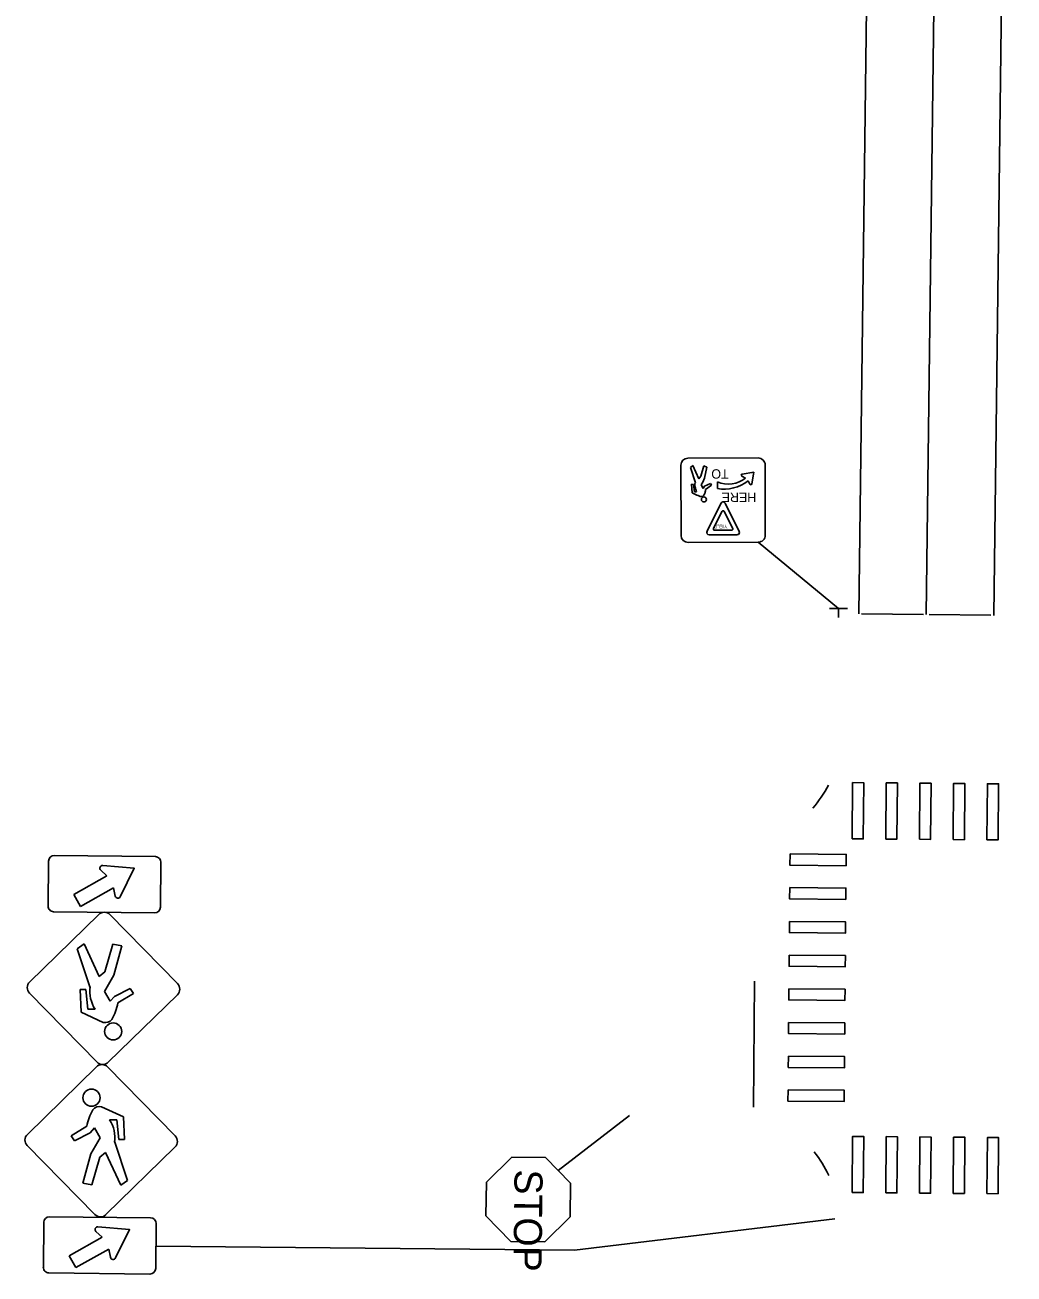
# Model space of a CAD drawing. Extents: x 1652376 to 1652707, y 605933 to 608571.
# Drawn here: x 1652376 to 1652552.1, y 606819.4 to 607041.8 of the extents above; entities that cross this region are included whole.
import ezdxf

# ---------------------------------------------------------------- set-up
doc = ezdxf.new("R2010")
doc.units = 0
for name, color, linetype in [('_CIVIL_CONSTRUCTION', 7, 'Continuous'), ('GE_P_Alignment', 7, 'Continuous'), ('PM_P_CL_Double_Solid', 7, 'Continuous'), ('PV_P_EOP', 7, 'Continuous'), ('SH_Border', 7, 'Continuous'), ('SH_Cut_Line', 7, 'Continuous'), ('SN_P_Signs', 7, 'Continuous'), ('SN_P_Text', 7, 'Continuous'), ('SN_X_Public', 7, 'Continuous'), ('UT_X_Misc_Cells', 7, 'Continuous')]:
    doc.layers.add(name, color=color, linetype=linetype)

msp = doc.modelspace()

# ---------------------------------------------------------------- linework, layer by layer
at = {"layer": '_CIVIL_CONSTRUCTION'}
for points in [[(1652523.24, 606896.95), (1652525.24, 606896.93), (1652525.33, 606906.93), (1652523.33, 606906.95)], [(1652529.24, 606896.9), (1652531.24, 606896.88), (1652531.33, 606906.88), (1652529.33, 606906.9)], [(1652535.24, 606896.85), (1652537.24, 606896.83), (1652537.33, 606906.83), (1652535.33, 606906.85)], [(1652541.24, 606896.8), (1652543.24, 606896.78), (1652543.33, 606906.78), (1652541.33, 606906.8)], [(1652547.24, 606896.75), (1652549.24, 606896.73), (1652549.33, 606906.73), (1652547.33, 606906.75)], [(1652512.21, 606894.24), (1652512.19, 606892.24), (1652522.19, 606892.15), (1652522.21, 606894.15)], [(1652512.16, 606888.24), (1652512.14, 606886.24), (1652522.14, 606886.15), (1652522.16, 606888.15)], [(1652512.11, 606882.24), (1652512.09, 606880.24), (1652522.09, 606880.15), (1652522.11, 606882.15)], [(1652512.06, 606876.24), (1652512.04, 606874.24), (1652522.04, 606874.15), (1652522.06, 606876.15)], [(1652512.01, 606870.24), (1652511.99, 606868.24), (1652521.99, 606868.15), (1652522.01, 606870.15)], [(1652511.96, 606864.24), (1652511.94, 606862.24), (1652521.94, 606862.15), (1652521.96, 606864.15)], [(1652511.91, 606858.24), (1652511.89, 606856.24), (1652521.89, 606856.15), (1652521.91, 606858.15)], [(1652511.85, 606852.24), (1652511.84, 606850.24), (1652521.84, 606850.15), (1652521.85, 606852.15)], [(1652523.24, 606833.95), (1652525.24, 606833.93), (1652525.33, 606843.93), (1652523.33, 606843.95)], [(1652529.24, 606833.9), (1652531.24, 606833.88), (1652531.33, 606843.88), (1652529.33, 606843.9)], [(1652535.24, 606833.85), (1652537.24, 606833.83), (1652537.33, 606843.83), (1652535.33, 606843.85)], [(1652541.24, 606833.8), (1652543.24, 606833.78), (1652543.33, 606843.78), (1652541.33, 606843.8)], [(1652547.24, 606833.75), (1652549.24, 606833.73), (1652549.33, 606843.73), (1652547.33, 606843.75)]]:
    msp.add_lwpolyline(points, close=True, dxfattribs=at)
at = {"layer": 'GE_P_Alignment'}
msp.add_lwpolyline([(1652536.46, 606936.85), (1652539.76, 607199.49), (1652540.08, 607225.63)], dxfattribs=at)
at = {"layer": 'PM_P_CL_Double_Solid'}
msp.add_lwpolyline([(1652524.46, 606937), (1652527.76, 607199.63), (1652528.08, 607225.77)], dxfattribs=at)
for centre, radius, start, end in [((1652492.93, 606921.21), 30, 321.1144, 330.6067), ((1652496.66, 606826.03), 25, 26.0343, 37.3992)]:
    msp.add_arc(centre, radius, start, end, dxfattribs=at)
at = {"layer": 'PV_P_EOP'}
msp.add_lwpolyline([(1652548.46, 606936.71), (1652551.76, 607199.34), (1652552.08, 607225.48)], dxfattribs=at)
at = {"layer": 'SH_Border'}
for p, q in [((1652389.88, 606892.17), (1652389.88, 606892.17)), ((1652384.74, 606887.02), (1652390.6, 606890.32)), ((1652390.6, 606890.32), (1652389.51, 606891.33)), ((1652391.79, 606888.2), (1652385.93, 606884.9)), ((1652392.09, 606886.75), (1652391.79, 606888.2)), ((1652385.93, 606884.9), (1652384.74, 606887.02)), ((1652385.35, 606877.37), (1652386.55, 606878.23)), ((1652386.55, 606878.23), (1652389.25, 606872.39)), ((1652390.25, 606873.25), (1652391.69, 606878.17)), ((1652391.69, 606878.17), (1652393.28, 606877.86)), ((1652387.65, 606870.38), (1652385.35, 606877.37)), ((1652393.28, 606877.86), (1652391.83, 606872.66)), ((1652389.25, 606872.39), (1652390.25, 606873.25)), ((1652391.83, 606872.66), (1652390.22, 606869.77)), ((1652386.02, 606866.04), (1652385.86, 606870.11)), ((1652385.86, 606870.11), (1652386.85, 606870.09)), ((1652386.85, 606870.09), (1652387.21, 606866.6)), ((1652390.22, 606869.77), (1652391.19, 606868.01)), ((1652391.99, 606868.88), (1652394.78, 606870.3)), ((1652395.36, 606869.42), (1652392.57, 606867.71)), ((1652394.78, 606870.3), (1652395.36, 606869.42)), ((1652391.19, 606868.01), (1652391.99, 606868.88)), ((1652389.96, 606864.25), (1652386.02, 606866.04)), ((1652387.21, 606866.6), (1652388.52, 606866.59)), ((1652389.66, 606849.22), (1652393.6, 606847.44)), ((1652393.6, 606847.44), (1652393.75, 606843.37)), ((1652384.26, 606844.06), (1652387.05, 606845.77)), ((1652388.43, 606845.46), (1652387.63, 606844.6)), ((1652389.4, 606843.71), (1652388.43, 606845.46)), ((1652392.41, 606846.87), (1652391.1, 606846.89)), ((1652392.76, 606843.38), (1652392.41, 606846.87)), ((1652384.84, 606843.18), (1652384.26, 606844.06)), ((1652387.63, 606844.6), (1652384.84, 606843.18)), ((1652387.78, 606840.82), (1652389.4, 606843.71)), ((1652391.97, 606843.1), (1652394.27, 606836.1)), ((1652393.75, 606843.37), (1652392.76, 606843.38)), ((1652386.34, 606835.61), (1652387.78, 606840.82)), ((1652390.36, 606841.09), (1652389.36, 606840.22)), ((1652393.07, 606835.25), (1652390.36, 606841.09)), ((1652389.36, 606840.22), (1652387.92, 606835.31)), ((1652462.71, 606840.23), (1652458.16, 606835.78)), ((1652468.71, 606840.16), (1652462.71, 606840.23)), ((1652473.16, 606835.61), (1652468.71, 606840.16)), ((1652394.27, 606836.1), (1652393.07, 606835.25)), ((1652387.92, 606835.31), (1652386.34, 606835.61)), ((1652458.16, 606835.78), (1652458.09, 606829.78)), ((1652473.09, 606829.61), (1652473.16, 606835.61)), ((1652458.09, 606829.78), (1652462.54, 606825.23)), ((1652468.54, 606825.16), (1652473.09, 606829.61)), ((1652389.75, 606826), (1652388.66, 606827.01)), ((1652389.03, 606827.85), (1652389.03, 606827.85)), ((1652383.89, 606822.7), (1652389.75, 606826)), ((1652462.54, 606825.23), (1652468.54, 606825.16)), ((1652385.08, 606820.58), (1652383.89, 606822.7)), ((1652390.94, 606823.88), (1652385.08, 606820.58)), ((1652391.24, 606822.43), (1652390.94, 606823.88))]:
    msp.add_line(p, q, dxfattribs=at)
for points in [[(1652399.25, 606893.76), (1652381.25, 606893.96)], [(1652380.24, 606892.97), (1652380.15, 606884.97)], [(1652389.88, 606892.17), (1652395.5, 606891.69), (1652393, 606886.63)], [(1652400.15, 606884.75), (1652400.24, 606892.75)], [(1652376.87, 606871.43), (1652389.17, 606883.46)], [(1652381.14, 606883.96), (1652399.14, 606883.76)], [(1652391.15, 606883.44), (1652403.18, 606871.15)], [(1652388.88, 606857.16), (1652376.85, 606869.45)], [(1652403.16, 606869.17), (1652390.86, 606857.14)], [(1652376.46, 606844.31), (1652388.76, 606856.34)], [(1652390.74, 606856.32), (1652402.76, 606844.02)], [(1652388.47, 606830.04), (1652376.44, 606842.33)], [(1652402.74, 606842.04), (1652390.45, 606830.01)], [(1652398.4, 606829.44), (1652380.4, 606829.64)], [(1652379.39, 606828.65), (1652379.31, 606820.65)], [(1652389.03, 606827.85), (1652394.65, 606827.36), (1652392.15, 606822.31)], [(1652399.3, 606820.43), (1652399.39, 606828.43)], [(1652380.29, 606819.64), (1652398.29, 606819.44)]]:
    msp.add_lwpolyline(points, dxfattribs=at)
for centre in [(1652391.74, 606862.64), (1652387.88, 606850.84)]:
    msp.add_circle(centre, 1.52, dxfattribs=at)
for centre, radius, start, end in [((1652381.24, 606892.96), 1, 89.3709, 179.3709), ((1652399.24, 606892.76), 1, 359.3709, 89.3709), ((1652389.84, 606891.69), 0.486, 85.0472, 227.1837), ((1652381.15, 606884.96), 1, 179.3709, 269.3709), ((1652392.57, 606886.84), 0.486, 191.5581, 333.6946), ((1652390.15, 606882.46), 1.4, 44.3709, 134.3709), ((1652399.15, 606884.76), 1, 269.3709, 359.3709), ((1652377.85, 606870.43), 1.4, 134.3709, 224.3709), ((1652393.23, 606869.7), 5.64, 171.2211, 213.4318), ((1652402.18, 606870.17), 1.4, 314.3709, 44.3709), ((1652383.04, 606869.49), 9.69, 330.912, 349.4026), ((1652390.33, 606865.71), 1.5, 255.615, 321.8659), ((1652389.73, 606855.34), 1.4, 44.3709, 134.3709), ((1652389.88, 606858.14), 1.4, 224.3709, 314.3709), ((1652389.29, 606847.77), 1.5, 75.615, 141.8659), ((1652396.57, 606843.98), 9.69, 150.912, 169.4026), ((1652386.39, 606843.77), 5.64, 351.2211, 33.4318), ((1652377.44, 606843.31), 1.4, 134.3709, 224.3709), ((1652401.76, 606843.04), 1.4, 314.3709, 44.3709), ((1652380.39, 606828.64), 1, 89.3709, 179.3709), ((1652389.47, 606831.01), 1.4, 224.3709, 314.3709), ((1652398.39, 606828.44), 1, 359.3709, 89.3709), ((1652388.99, 606827.36), 0.486, 85.0472, 227.1837), ((1652380.3, 606820.64), 1, 179.3709, 269.3709), ((1652391.72, 606822.52), 0.486, 191.5581, 333.6946), ((1652398.3, 606820.44), 1, 269.3709, 359.3709)]:
    msp.add_arc(centre, radius, start, end, dxfattribs=at)
at = {"layer": 'SH_Cut_Line'}
for p, q in [((1652535.95, 606936.86), (1652524.96, 606936.99)), ((1652547.95, 606936.76), (1652536.96, 606936.89))]:
    msp.add_line(p, q, dxfattribs=at)
at = {"layer": 'SN_P_Signs'}
msp.add_line((1652506.56, 606949.75), (1652520.83, 606937.92), dxfattribs=at)
at = {"layer": 'SN_P_Text'}
for p, q in [((1652494.93, 606963.41), (1652494.47, 606963.06)), ((1652494.47, 606963.06), (1652495.39, 606960.35)), ((1652495.96, 606961.06), (1652494.93, 606963.41)), ((1652496.87, 606963.37), (1652496.33, 606961.53)), ((1652497.4, 606963.11), (1652496.87, 606963.37)), ((1652496.98, 606961.14), (1652497.4, 606963.11)), ((1652496.33, 606961.53), (1652495.96, 606961.06)), ((1652496.42, 606959.99), (1652496.67, 606960.47)), ((1652496.67, 606960.47), (1652496.98, 606961.14)), ((1652499.28, 606959.29), (1652499.28, 606960.52)), ((1652504.3, 606961.18), (1652503.62, 606961.53)), ((1652503.67, 606961.87), (1652505.79, 606962.25)), ((1652505.08, 606960.08), (1652504.76, 606960.69)), ((1652505.79, 606962.25), (1652505.42, 606960.13)), ((1652495, 606960.05), (1652494.66, 606960.08)), ((1652494.66, 606960.08), (1652494.79, 606958.52)), ((1652494.79, 606958.52), (1652494.8, 606958.52)), ((1652495.19, 606958.73), (1652495, 606960.05)), ((1652495.57, 606958.72), (1652495.19, 606958.73)), ((1652495.39, 606960.35), (1652495.34, 606960.29)), ((1652496.77, 606959.29), (1652496.42, 606959.99)), ((1652497, 606959.72), (1652496.77, 606959.29)), ((1652498.03, 606960.21), (1652497, 606959.72)), ((1652497.19, 606959.12), (1652498.24, 606959.9)), ((1652498.24, 606959.9), (1652498.03, 606960.21)), ((1652500.65, 606956.7), (1652503.18, 606951.66)), ((1652500.51, 606955.23), (1652502.02, 606952.21)), ((1652498.8, 606951.87), (1652501.82, 606951.88)), ((1652502.83, 606951.09), (1652497.79, 606951.08)), ((1652499.8, 606951.08), (1652499.81, 606951.09)), ((1652502.77, 606951.09), (1652502.77, 606951.09)), ((1652519.23, 606937.92), (1652522.43, 606937.92)), ((1652520.83, 606937.92), (1652520.83, 606936.32))]:
    msp.add_line(p, q, dxfattribs=at)
for points in [[(1652492.78, 606963.46), (1652492.81, 606950.96)], [(1652506.52, 606964.75), (1652494.02, 606964.71)], [(1652507.81, 606951), (1652507.78, 606963.5)], [(1652497.43, 606951.65), (1652499.94, 606956.7)], [(1652498.59, 606952.21), (1652500.09, 606955.22)], [(1652494.06, 606949.71), (1652506.56, 606949.75)]]:
    msp.add_lwpolyline(points, dxfattribs=at)
msp.add_circle((1652496.89, 606957.36), 0.45, dxfattribs=at)
for centre, radius, start, end in [((1652494.03, 606963.46), 1.25, 90.1516, 180.1516), ((1652506.53, 606963.5), 1.25, 0.1516, 90.1516), ((1652501.26, 606964.94), 4.84, 245.8938, 309.0288), ((1652500.46, 606966.1), 6.91, 260.1665, 308.517), ((1652503.71, 606961.69), 0.181, 100.0723, 242.7894), ((1652505.24, 606960.16), 0.181, 207.5138, 350.2308), ((1652500.3, 606956.52), 0.395, 26.7166, 153.5865), ((1652500.3, 606955.12), 0.232, 26.7166, 153.5865), ((1652497.79, 606951.47), 0.395, 153.5865, 270.1516), ((1652498.8, 606952.1), 0.232, 153.5865, 270.1516), ((1652501.82, 606952.11), 0.232, 270.1516, 26.7166), ((1652502.83, 606951.49), 0.395, 270.1516, 26.7166), ((1652494.06, 606950.96), 1.25, 180.1516, 270.1516), ((1652506.56, 606951), 1.25, 270.1516, 0.1516)]:
    msp.add_arc(centre, radius, start, end, dxfattribs=at)
for points in [[(1652494.8, 606958.52), (1652495.26, 606958.32), (1652495.98, 606957.99), (1652496.24, 606957.87), (1652496.33, 606957.86), (1652496.42, 606957.86), (1652496.63, 606957.86), (1652496.89, 606958.11), (1652497.03, 606958.5), (1652497.16, 606958.79), (1652497.19, 606959.12)], [(1652495.34, 606960.29), (1652495.29, 606960.21), (1652495.24, 606960.08), (1652495.26, 606959.82), (1652495.31, 606959.6), (1652495.41, 606959.23), (1652495.49, 606958.96), (1652495.57, 606958.72)]]:
    msp.add_open_spline(points, degree=3, dxfattribs=at)
at = {"layer": 'SN_X_Public'}
msp.add_line((1652505.72, 606849.16), (1652505.91, 606871.6), dxfattribs=at)
at = {"layer": 'UT_X_Misc_Cells'}
msp.add_line((1652470.92, 606837.9), (1652483.66, 606847.67), dxfattribs=at)
msp.add_lwpolyline([(1652399.35, 606824.43), (1652473.87, 606823.7), (1652520.18, 606829.25)], dxfattribs=at)

# ---------------------------------------------------------------- texts
at = {"layer": 'SH_Border'}
msp.add_text('STOP', height=5, rotation=269.3709, dxfattribs=at).set_placement((1652463.18, 606838.09))
at = {"layer": 'SN_P_Text'}
for s, height, p in [('TO', 1.667, (1652501.29, 606962.75)), ('HERE', 1.667, (1652506.21, 606958.6)), ('YIELD', 0.608, (1652501.05, 606952.85))]:
    msp.add_text(s, height=height, rotation=180.1516, dxfattribs=at).set_placement(p)

doc.saveas('drawing.dxf')
